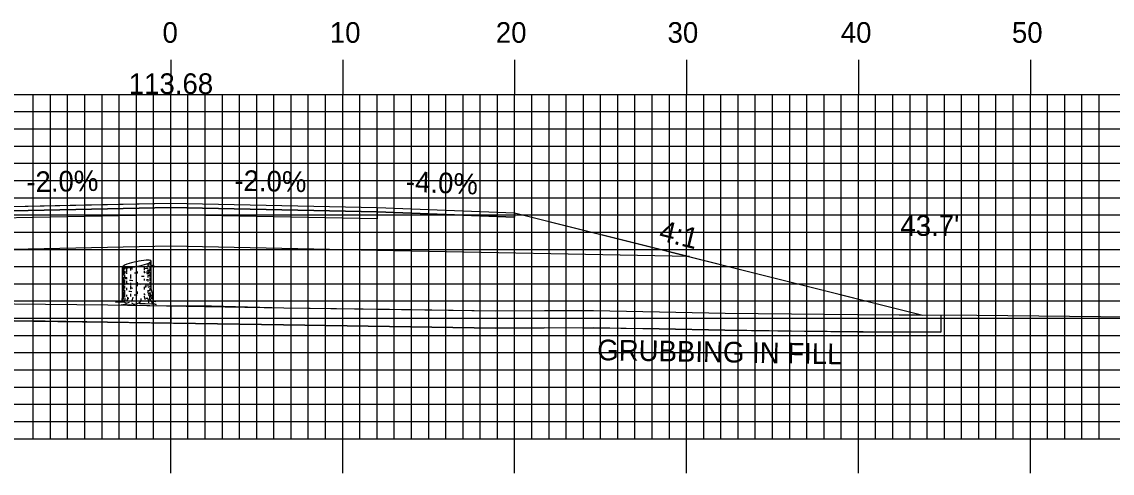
# Model space of a CAD drawing. Extents: x 1773203 to 1773546, y 442591 to 442811.
# Drawn here: x 1773360 to 1773423.4, y 442646.7 to 442672.9 of the extents above; entities that cross this region are included whole.
import ezdxf

# ---------------------------------------------------------------- set-up
doc = ezdxf.new("R2010")
doc.units = 0
for name, color, linetype in [('ANNOTATION', 7, 'Continuous'), ('D_Drainage_Culvert', 7, 'Continuous'), ('D_Roadway_Centerline', 7, 'Continuous'), ('D_Roadway_Centerline_Text', 7, 'Continuous'), ('D_Roadway_Edge_Shoulder', 7, 'Continuous'), ('D_Roadway_Edge_TW', 7, 'Continuous'), ('D_Roadway_Pavement', 7, 'Continuous'), ('D_Roadway_SubGrade', 7, 'Continuous'), ('D_Text_Standard', 7, 'Continuous'), ('GRUBBING IN FILL', 7, 'Continuous'), ('H_V ANNOTATION', 7, 'Continuous'), ('M_Trees_Conifer_Pay', 7, 'Continuous'), ('MAJOR', 7, 'Continuous'), ('MINOR', 7, 'Continuous'), ('S_Roadway_Centerline', 7, 'Continuous')]:
    doc.layers.add(name, color=color, linetype=linetype)

msp = doc.modelspace()

# ---------------------------------------------------------------- linework, layer by layer
at = {"layer": 'D_Drainage_Culvert'}
msp.add_line((1773380.633, 442662.104), (1773388.632, 442661.784), dxfattribs=at)
msp.add_lwpolyline([(1773388.632, 442661.784), (1773392.632, 442660.784), (1773412.369, 442655.85)], dxfattribs=at)
at = {"layer": 'D_Roadway_Centerline'}
msp.add_lwpolyline([(1773330.914, 442657.355), (1773338.457, 442659.24), (1773348.633, 442661.784), (1773348.633, 442661.784), (1773348.633, 442661.784), (1773352.008, 442661.919), (1773356.633, 442662.104), (1773363.648, 442662.245), (1773368.633, 442662.344), (1773380.633, 442662.104), (1773388.632, 442661.784), (1773388.632, 442661.784), (1773412.369, 442655.85)], dxfattribs=at)
at = {"layer": 'D_Roadway_Edge_Shoulder'}
msp.add_lwpolyline([(1773380.633, 442662.104), (1773388.632, 442661.784), (1773388.633, 442661.534), (1773380.633, 442661.854)], close=True, dxfattribs=at)
at = {"layer": 'D_Roadway_Edge_TW'}
msp.add_lwpolyline([(1773356.633, 442661.854), (1773356.633, 442662.104), (1773368.633, 442662.344), (1773380.633, 442662.104), (1773380.633, 442661.854), (1773368.633, 442662.094)], close=True, dxfattribs=at)
at = {"layer": 'D_Roadway_Pavement'}
msp.add_lwpolyline([(1773356.633, 442661.437), (1773356.633, 442661.854), (1773368.633, 442662.094), (1773380.633, 442661.854), (1773380.633, 442661.437), (1773368.633, 442661.677)], close=True, dxfattribs=at)
at = {"layer": 'D_Roadway_SubGrade'}
msp.add_lwpolyline([(1773356.633, 442659.604), (1773338.457, 442659.24), (1773348.633, 442661.784), (1773348.633, 442661.534), (1773356.633, 442661.854), (1773368.633, 442662.094), (1773380.633, 442661.854), (1773388.633, 442661.534), (1773388.632, 442661.784), (1773398.809, 442659.24), (1773380.633, 442659.604), (1773368.633, 442659.844)], close=True, dxfattribs=at)
at = {"layer": 'GRUBBING IN FILL'}
msp.add_line((1773413.42, 442655.845), (1773413.42, 442654.845), dxfattribs=at)
msp.add_line((1773413.42, 442655.845), (1773413.42, 442654.845), dxfattribs=at)
for points in [[(1773338.457, 442657.187), (1773343.237, 442657.056), (1773348.011, 442656.876), (1773352.869, 442656.7), (1773357.726, 442656.524), (1773361.346, 442656.483), (1773364.965, 442656.443), (1773368.633, 442656.382), (1773368.633, 442655.382), (1773364.952, 442655.443), (1773361.327, 442655.483), (1773357.703, 442655.524), (1773352.84, 442655.7), (1773347.977, 442655.877), (1773346.684, 442655.918), (1773340.829, 442656.122), (1773338.457, 442656.187)], [(1773338.457, 442657.187), (1773343.237, 442657.056), (1773348.011, 442656.876), (1773352.869, 442656.7), (1773357.726, 442656.524), (1773361.346, 442656.483), (1773364.965, 442656.443), (1773368.633, 442656.382), (1773368.633, 442655.382), (1773364.952, 442655.443), (1773361.327, 442655.483), (1773357.703, 442655.524), (1773352.84, 442655.7), (1773347.977, 442655.877), (1773346.684, 442655.918), (1773340.829, 442656.122), (1773338.457, 442656.187)], [(1773368.633, 442656.382), (1773371.006, 442656.382), (1773375.201, 442656.273), (1773381.356, 442656.18), (1773387.511, 442656.088), (1773390.365, 442656.103), (1773393.22, 442656.117), (1773397.053, 442656.041), (1773400.886, 442655.965), (1773404.733, 442655.917), (1773408.579, 442655.87), (1773413.42, 442655.845), (1773413.42, 442654.845), (1773410.995, 442654.857), (1773404.72, 442654.917), (1773400.869, 442654.965), (1773397.041, 442655.041), (1773390.359, 442655.103), (1773387.506, 442655.088), (1773381.345, 442655.18), (1773375.185, 442655.273), (1773370.068, 442655.358), (1773368.633, 442655.382)], [(1773368.633, 442656.382), (1773371.006, 442656.382), (1773375.201, 442656.273), (1773381.356, 442656.18), (1773387.511, 442656.088), (1773390.365, 442656.103), (1773393.22, 442656.117), (1773397.053, 442656.041), (1773400.886, 442655.965), (1773404.733, 442655.917), (1773408.579, 442655.87), (1773413.42, 442655.845), (1773413.42, 442654.845), (1773410.995, 442654.857), (1773404.72, 442654.917), (1773400.869, 442654.965), (1773397.041, 442655.041), (1773390.359, 442655.103), (1773387.506, 442655.088), (1773381.345, 442655.18), (1773375.185, 442655.273), (1773370.068, 442655.358), (1773368.633, 442655.382)]]:
    msp.add_lwpolyline(points, close=True, dxfattribs=at)
msp.add_lwpolyline([(1773338.457, 442656.187), (1773343.201, 442656.057), (1773345.391, 442655.959), (1773347.977, 442655.877), (1773357.703, 442655.524), (1773364.952, 442655.443), (1773375.185, 442655.273), (1773387.506, 442655.088), (1773393.213, 442655.117), (1773400.869, 442654.965), (1773408.571, 442654.87), (1773413.42, 442654.845)], dxfattribs=at)
msp.add_lwpolyline([(1773338.457, 442656.187), (1773343.201, 442656.057), (1773345.391, 442655.959), (1773347.977, 442655.877), (1773357.703, 442655.524), (1773364.952, 442655.443), (1773375.185, 442655.273), (1773387.506, 442655.088), (1773393.213, 442655.117), (1773400.869, 442654.965), (1773408.571, 442654.87), (1773413.42, 442654.845)], dxfattribs=at)
at = {"layer": 'M_Trees_Conifer_Pay'}
for p, q in [((1773365.83, 442656.924), (1773365.83, 442658.646)), ((1773367.077, 442658.652), (1773367.077, 442658.452)), ((1773367.305, 442658.848), (1773367.305, 442658.625)), ((1773367.423, 442658.909), (1773367.423, 442658.746)), ((1773367.423, 442658.679), (1773367.423, 442658.551)), ((1773367.494, 442657.334), (1773367.494, 442658.981)), ((1773365.877, 442658.608), (1773365.877, 442658.137)), ((1773365.877, 442658.073), (1773365.877, 442657.765)), ((1773365.936, 442658.597), (1773365.936, 442658.499)), ((1773365.936, 442658.425), (1773365.936, 442658.221)), ((1773365.936, 442658.163), (1773365.936, 442657.964)), ((1773366.061, 442658.589), (1773366.061, 442658.357)), ((1773366.061, 442658.316), (1773366.061, 442658.242)), ((1773366.281, 442658.61), (1773366.281, 442658.442)), ((1773366.281, 442658.205), (1773366.281, 442657.968)), ((1773366.686, 442658.378), (1773366.686, 442658.283)), ((1773367.077, 442658.394), (1773367.077, 442658.306)), ((1773367.305, 442658.536), (1773367.305, 442658.489)), ((1773367.305, 442658.154), (1773367.305, 442658.022)), ((1773367.362, 442658.353), (1773367.311, 442658.293)), ((1773367.423, 442658.364), (1773367.423, 442658.028)), ((1773365.877, 442657.717), (1773365.877, 442657.225)), ((1773365.936, 442657.917), (1773365.936, 442657.581)), ((1773365.936, 442657.528), (1773365.936, 442657.392)), ((1773366.061, 442657.839), (1773366.061, 442657.7)), ((1773366.061, 442657.429), (1773366.061, 442657.287)), ((1773366.281, 442657.723), (1773366.281, 442657.571)), ((1773366.281, 442657.528), (1773366.281, 442657.354)), ((1773366.686, 442657.765), (1773366.686, 442657.69)), ((1773366.686, 442657.665), (1773366.686, 442657.517)), ((1773367.077, 442657.958), (1773367.077, 442657.853)), ((1773367.077, 442657.486), (1773367.077, 442657.34)), ((1773367.305, 442657.911), (1773367.305, 442657.801)), ((1773367.305, 442657.665), (1773367.305, 442657.524)), ((1773367.423, 442657.991), (1773367.423, 442657.828)), ((1773367.423, 442657.781), (1773367.423, 442657.564)), ((1773367.423, 442657.534), (1773367.423, 442657.459)), ((1773367.423, 442657.419), (1773367.423, 442657.246)), ((1773365.877, 442657.171), (1773365.877, 442656.924)), ((1773365.936, 442657.293), (1773365.936, 442656.914)), ((1773366.061, 442657.025), (1773366.061, 442656.931)), ((1773366.281, 442657.077), (1773366.281, 442656.924)), ((1773366.686, 442657.225), (1773366.686, 442657.072)), ((1773367.077, 442657.108), (1773367.077, 442657.019)), ((1773367.305, 442657.297), (1773367.305, 442657.124)), ((1773366.061, 442656.531), (1773366.224, 442656.595)), ((1773366.498, 442656.467), (1773366.372, 442656.531))]:
    msp.add_line(p, q, dxfattribs=at)
for points in [[(1773367.311, 442658.479), (1773367.348, 442658.405), (1773367.395, 442658.462), (1773367.453, 442658.53), (1773367.545, 442658.724), (1773367.61, 442658.771), (1773367.64, 442658.778)], [(1773367.326, 442658.226), (1773367.362, 442658.353), (1773367.426, 442658.469), (1773367.457, 442658.536), (1773367.526, 442658.683)], [(1773367.54, 442658.712), (1773367.616, 442658.72), (1773367.688, 442658.621)], [(1773366.009, 442657.952), (1773366.003, 442658.047), (1773366.047, 442658.024), (1773366.047, 442657.929)], [(1773367.278, 442658.442), (1773367.247, 442658.357), (1773367.243, 442658.289), (1773367.274, 442658.226)], [(1773367.148, 442657.553), (1773367.161, 442657.476), (1773367.208, 442657.486), (1773367.196, 442657.653)], [(1773367.494, 442657.334), (1773367.545, 442657.072), (1773367.562, 442656.799), (1773367.619, 442656.673), (1773367.755, 442656.643), (1773367.525, 442656.605), (1773367.525, 442656.605), (1773367.531, 442656.558), (1773367.778, 442656.463), (1773367.504, 442656.48), (1773367.148, 442656.5), (1773366.827, 442656.49), (1773366.833, 442656.572), (1773366.685, 442656.49), (1773366.498, 442656.467), (1773366.522, 442656.399), (1773366.255, 442656.442), (1773366.034, 442656.415), (1773365.742, 442656.433), (1773366.03, 442656.49), (1773366.061, 442656.531), (1773365.898, 442656.589), (1773365.661, 442656.599), (1773365.421, 442656.599), (1773365.763, 442656.657), (1773365.804, 442656.737), (1773365.83, 442656.924)], [(1773365.878, 442656.877), (1773365.857, 442656.799), (1773365.837, 442656.704)], [(1773365.956, 442656.856), (1773365.962, 442656.741), (1773365.909, 442656.652), (1773365.898, 442656.589)], [(1773366.119, 442656.883), (1773366.119, 442656.751), (1773366.03, 442656.652)], [(1773366.345, 442656.643), (1773366.413, 442656.737), (1773366.44, 442656.877)], [(1773366.833, 442656.572), (1773366.908, 442656.714), (1773366.917, 442656.815)], [(1773367.084, 442656.941), (1773367.095, 442656.815), (1773367.169, 442656.772)], [(1773367.362, 442656.552), (1773367.348, 442656.69), (1773367.274, 442656.819)], [(1773367.321, 442657.046), (1773367.395, 442656.941), (1773367.4, 442656.768), (1773367.525, 442656.605)], [(1773367.42, 442657.192), (1773367.426, 442657.046), (1773367.473, 442656.978), (1773367.484, 442656.778)]]:
    msp.add_lwpolyline(points, dxfattribs=at)
for centre, radius, start, end in [((1773365.857, 442658.645), 0.0264, 169.2194, 180.03145), ((1773365.853, 442658.645), 0.0226, 180.03145, 191.7194), ((1773365.862, 442658.645), 0.0314, 156.51582, 169.2194), ((1773365.853, 442658.645), 0.0226, 191.7194, 203.40735), ((1773365.881, 442658.636), 0.0527, 146.7194, 156.51582), ((1773365.905, 442658.62), 0.0817, 132.38868, 146.7194), ((1773366.019, 442658.495), 0.251, 124.2194, 132.38868), ((1773366.329, 442658.04), 0.802, 108.05939, 124.2194), ((1773367.686, 442653.878), 5.179, 101.7194, 108.05939), ((1773365.638, 442663.749), 5.179, 275.37941, 281.7194), ((1773367.686, 442653.878), 5.179, 95.37941, 101.7194), ((1773365.638, 442663.749), 5.179, 281.7194, 288.05939), ((1773367.276, 442658.236), 0.802, 79.2194, 95.37941), ((1773366.995, 442659.587), 0.802, 288.05939, 304.2194), ((1773367.163, 442659.295), 0.571, 284.43166, 292.41325), ((1773367.163, 442659.14), 0.571, 297.0237, 300), ((1773367.379, 442658.777), 0.251, 71.05013, 79.2194), ((1773367.305, 442659.131), 0.251, 304.2194, 312.38868), ((1773367.362, 442658.95), 0.172, 300, 311.25059), ((1773367.362, 442658.795), 0.172, 300, 311.25059), ((1773367.434, 442658.937), 0.0817, 56.7194, 71.05013), ((1773367.419, 442659.007), 0.0817, 312.38868, 326.7194), ((1773367.435, 442658.867), 0.0624, 311.25059, 330), ((1773367.435, 442658.713), 0.0624, 311.25059, 330), ((1773367.449, 442658.961), 0.0527, 46.92298, 56.7194), ((1773367.464, 442658.977), 0.0314, 34.2194, 46.92298), ((1773367.443, 442658.991), 0.0527, 326.7194, 336.51582), ((1773367.451, 442658.858), 0.0441, 330, 343.94846), ((1773367.451, 442658.703), 0.0441, 330, 343.94846), ((1773367.468, 442658.98), 0.0264, 23.40735, 34.2194), ((1773367.472, 442658.981), 0.0226, 11.7194, 23.40735), ((1773367.463, 442658.982), 0.0314, 336.51582, 349.2194), ((1773367.461, 442658.855), 0.0334, 343.94846, 354.21506), ((1773367.461, 442658.7), 0.0334, 343.94846, 354.21506), ((1773367.472, 442658.981), 0.0226, 0.03145, 11.7194), ((1773367.468, 442658.981), 0.0264, 349.2194, 0.03145), ((1773365.862, 442658.468), 0.0334, 163.94846, 180), ((1773365.862, 442658.468), 0.0334, 180, 196.05154), ((1773365.862, 442658.021), 0.0334, 163.94846, 180), ((1773365.862, 442658.021), 0.0334, 180, 196.05154), ((1773365.873, 442658.47), 0.0441, 196.05154, 210), ((1773365.873, 442658.024), 0.0441, 196.05154, 210), ((1773365.856, 442658.647), 0.0264, 203.40735, 214.2194), ((1773365.86, 442658.65), 0.0314, 214.2194, 226.92298), ((1773365.888, 442658.48), 0.0624, 210, 228.74941), ((1773365.875, 442658.665), 0.0527, 226.92298, 236.7194), ((1773365.891, 442658.69), 0.0817, 236.7194, 251.05013), ((1773365.961, 442658.562), 0.172, 228.74941, 240), ((1773365.946, 442658.849), 0.251, 251.05013, 259.2194), ((1773366.16, 442658.907), 0.571, 240, 240.33672), ((1773366.161, 442658.696), 0.571, 240, 247.05866), ((1773366.049, 442659.391), 0.802, 259.2194, 275.37941), ((1773366.16, 442658.907), 0.571, 246.85973, 257.98457), ((1773366.662, 442662.658), 4.124, 264.6955, 266.73309), ((1773366.661, 442662.425), 4.124, 268.07512, 270), ((1773366.661, 442662.425), 4.124, 270, 270.35814), ((1773366.662, 442662.214), 4.124, 273.70524, 275.95043), ((1773366.661, 442662.425), 4.124, 275.78493, 277.05584), ((1773366.662, 442662.658), 4.124, 276.23804, 278.1032), ((1773367.163, 442659.14), 0.571, 278.1032, 284.36665), ((1773367.163, 442658.696), 0.571, 284.44928, 297.04285), ((1773367.449, 442658.024), 0.0441, 330, 343.94846), ((1773367.46, 442658.021), 0.0334, 343.94846, 354.21506), ((1773367.461, 442658.256), 0.0334, 343.94846, 354.21506), ((1773365.862, 442657.811), 0.0334, 163.94846, 180), ((1773365.862, 442657.811), 0.0334, 180, 196.05154), ((1773365.862, 442657.574), 0.0334, 163.94846, 180), ((1773365.862, 442657.574), 0.0334, 180, 196.05154), ((1773365.862, 442657.376), 0.0334, 163.94846, 180), ((1773365.873, 442657.814), 0.0441, 196.05154, 210), ((1773365.873, 442657.577), 0.0441, 196.05154, 210), ((1773365.888, 442658.033), 0.0624, 210, 228.74941), ((1773365.888, 442657.823), 0.0624, 210, 228.74941), ((1773365.888, 442657.586), 0.0624, 210, 228.74941), ((1773365.961, 442658.115), 0.172, 228.74941, 240), ((1773365.961, 442657.905), 0.172, 228.74941, 240), ((1773365.961, 442657.669), 0.172, 228.74941, 240), ((1773366.16, 442658.461), 0.571, 240, 240.33672), ((1773366.16, 442658.25), 0.571, 240, 246.85973), ((1773366.16, 442658.014), 0.571, 240, 246.85973), ((1773366.16, 442658.25), 0.571, 259.27072, 261.8968), ((1773366.661, 442661.768), 4.124, 261.8968, 263.14738), ((1773366.661, 442661.978), 4.124, 264.08098, 266.66759), ((1773366.661, 442661.531), 4.124, 264.71603, 266.31934), ((1773366.661, 442661.768), 4.124, 270, 270.35814), ((1773366.661, 442661.768), 4.124, 273.14934, 275.45691), ((1773366.661, 442661.978), 4.124, 277.61247, 278.1032), ((1773367.162, 442658.461), 0.571, 278.1032, 286.92962), ((1773367.162, 442658.014), 0.571, 285.39827, 297.18959), ((1773367.162, 442658.461), 0.571, 297.18959, 300), ((1773367.162, 442658.25), 0.571, 297.18959, 300), ((1773367.361, 442658.115), 0.172, 300, 311.25059), ((1773367.361, 442657.905), 0.172, 300, 311.25059), ((1773367.433, 442658.033), 0.0624, 311.25059, 330), ((1773367.433, 442657.823), 0.0624, 311.25059, 330), ((1773367.449, 442657.814), 0.0441, 330, 343.94846), ((1773367.46, 442657.811), 0.0334, 343.94846, 354.21506), ((1773367.46, 442657.376), 0.0334, 343.94846, 354.21506), ((1773365.862, 442657.181), 0.0334, 163.94846, 180), ((1773365.862, 442657.181), 0.0334, 180, 196.05154), ((1773365.862, 442656.96), 0.0334, 163.94846, 180), ((1773365.862, 442656.96), 0.0334, 180, 196.05154), ((1773365.873, 442657.184), 0.0441, 196.05154, 210), ((1773365.873, 442656.963), 0.0441, 196.05154, 210), ((1773365.888, 442657.193), 0.0624, 210, 228.74941), ((1773365.888, 442656.972), 0.0624, 210, 228.74941), ((1773365.961, 442657.275), 0.172, 228.74941, 240), ((1773365.961, 442657.055), 0.172, 228.74941, 240), ((1773366.149, 442657.822), 0.571, 241.23686, 248.02677), ((1773366.16, 442657.62), 0.571, 240, 246.85973), ((1773366.16, 442657.4), 0.571, 240, 244.53138), ((1773366.661, 442660.918), 4.124, 262.44379, 263.51202), ((1773366.661, 442661.334), 4.124, 263.49906, 265.83975), ((1773366.661, 442661.138), 4.124, 267.81166, 270), ((1773366.661, 442661.138), 4.124, 270, 270.13279), ((1773366.661, 442661.138), 4.124, 275.78493, 276.78961), ((1773366.661, 442660.918), 4.124, 277.36842, 278.1032), ((1773367.162, 442657.4), 0.571, 278.1032, 281.63703), ((1773367.162, 442657.62), 0.571, 288.50673, 297.27208), ((1773367.162, 442657.816), 0.571, 289.29072, 300), ((1773367.361, 442657.471), 0.172, 300, 311.25059), ((1773367.361, 442657.055), 0.172, 300, 311.25059), ((1773367.433, 442657.388), 0.0624, 311.25059, 330), ((1773367.433, 442656.972), 0.0624, 311.25059, 330), ((1773367.449, 442657.379), 0.0441, 330, 343.94846), ((1773367.449, 442656.963), 0.0441, 330, 343.94846), ((1773367.46, 442656.96), 0.0334, 343.94846, 354.21506)]:
    msp.add_arc(centre, radius, start, end, dxfattribs=at)
at = {"layer": 'MAJOR'}
for p, q in [((1773368.633, 442670.669), (1773368.633, 442668.665)), ((1773378.633, 442670.669), (1773378.633, 442668.665)), ((1773388.633, 442670.669), (1773388.633, 442668.665)), ((1773398.633, 442670.669), (1773398.633, 442668.665)), ((1773408.633, 442670.669), (1773408.633, 442668.665)), ((1773418.633, 442670.669), (1773418.633, 442668.665)), ((1773228.633, 442668.665), (1773508.633, 442668.665)), ((1773228.633, 442668.665), (1773508.633, 442668.665)), ((1773368.633, 442648.665), (1773368.633, 442668.665)), ((1773378.633, 442648.665), (1773378.633, 442668.665)), ((1773388.633, 442648.665), (1773388.633, 442668.665)), ((1773398.633, 442648.665), (1773398.633, 442668.665)), ((1773408.633, 442648.665), (1773408.633, 442668.665)), ((1773418.633, 442648.665), (1773418.633, 442668.665)), ((1773228.633, 442663.665), (1773508.633, 442663.665)), ((1773228.633, 442658.665), (1773508.633, 442658.665)), ((1773228.633, 442653.665), (1773508.633, 442653.665)), ((1773228.633, 442648.665), (1773508.633, 442648.665)), ((1773228.633, 442648.665), (1773508.633, 442648.665)), ((1773368.633, 442646.661), (1773368.633, 442648.665)), ((1773378.633, 442646.661), (1773378.633, 442648.665)), ((1773388.633, 442646.661), (1773388.633, 442648.665)), ((1773398.633, 442646.661), (1773398.633, 442648.665)), ((1773408.633, 442646.661), (1773408.633, 442648.665)), ((1773418.633, 442646.661), (1773418.633, 442648.665))]:
    msp.add_line(p, q, dxfattribs=at)
at = {"layer": 'MINOR'}
for p, q in [((1773360.633, 442648.665), (1773360.633, 442668.665)), ((1773361.633, 442648.665), (1773361.633, 442668.665)), ((1773362.633, 442648.665), (1773362.633, 442668.665)), ((1773363.633, 442648.665), (1773363.633, 442668.665)), ((1773364.633, 442648.665), (1773364.633, 442668.665)), ((1773365.633, 442648.665), (1773365.633, 442668.665)), ((1773366.633, 442648.665), (1773366.633, 442668.665)), ((1773367.633, 442648.665), (1773367.633, 442668.665)), ((1773369.633, 442648.665), (1773369.633, 442668.665)), ((1773370.633, 442648.665), (1773370.633, 442668.665)), ((1773371.633, 442648.665), (1773371.633, 442668.665)), ((1773372.633, 442648.665), (1773372.633, 442668.665)), ((1773373.633, 442648.665), (1773373.633, 442668.665)), ((1773374.633, 442648.665), (1773374.633, 442668.665)), ((1773375.633, 442648.665), (1773375.633, 442668.665)), ((1773376.633, 442648.665), (1773376.633, 442668.665)), ((1773377.633, 442648.665), (1773377.633, 442668.665)), ((1773379.633, 442648.665), (1773379.633, 442668.665)), ((1773380.633, 442648.665), (1773380.633, 442668.665)), ((1773381.633, 442648.665), (1773381.633, 442668.665)), ((1773382.633, 442648.665), (1773382.633, 442668.665)), ((1773383.633, 442648.665), (1773383.633, 442668.665)), ((1773384.633, 442648.665), (1773384.633, 442668.665)), ((1773385.633, 442648.665), (1773385.633, 442668.665)), ((1773386.633, 442648.665), (1773386.633, 442668.665)), ((1773387.633, 442648.665), (1773387.633, 442668.665)), ((1773389.633, 442648.665), (1773389.633, 442668.665)), ((1773390.633, 442648.665), (1773390.633, 442668.665)), ((1773391.633, 442648.665), (1773391.633, 442668.665)), ((1773392.633, 442648.665), (1773392.633, 442668.665)), ((1773393.633, 442648.665), (1773393.633, 442668.665)), ((1773394.633, 442648.665), (1773394.633, 442668.665)), ((1773395.633, 442648.665), (1773395.633, 442668.665)), ((1773396.633, 442648.665), (1773396.633, 442668.665)), ((1773397.633, 442648.665), (1773397.633, 442668.665)), ((1773399.633, 442648.665), (1773399.633, 442668.665)), ((1773400.633, 442648.665), (1773400.633, 442668.665)), ((1773401.633, 442648.665), (1773401.633, 442668.665)), ((1773402.633, 442648.665), (1773402.633, 442668.665)), ((1773403.633, 442648.665), (1773403.633, 442668.665)), ((1773404.633, 442648.665), (1773404.633, 442668.665)), ((1773405.633, 442648.665), (1773405.633, 442668.665)), ((1773406.633, 442648.665), (1773406.633, 442668.665)), ((1773407.633, 442648.665), (1773407.633, 442668.665)), ((1773409.633, 442648.665), (1773409.633, 442668.665)), ((1773410.633, 442648.665), (1773410.633, 442668.665)), ((1773411.633, 442648.665), (1773411.633, 442668.665)), ((1773412.633, 442648.665), (1773412.633, 442668.665)), ((1773413.633, 442648.665), (1773413.633, 442668.665)), ((1773414.633, 442648.665), (1773414.633, 442668.665)), ((1773415.633, 442648.665), (1773415.633, 442668.665)), ((1773416.633, 442648.665), (1773416.633, 442668.665)), ((1773417.633, 442648.665), (1773417.633, 442668.665)), ((1773419.633, 442648.665), (1773419.633, 442668.665)), ((1773420.633, 442648.665), (1773420.633, 442668.665)), ((1773421.633, 442648.665), (1773421.633, 442668.665)), ((1773422.633, 442648.665), (1773422.633, 442668.665)), ((1773228.633, 442667.665), (1773508.633, 442667.665)), ((1773228.633, 442666.665), (1773508.633, 442666.665)), ((1773228.633, 442665.665), (1773508.633, 442665.665)), ((1773228.633, 442664.665), (1773508.633, 442664.665)), ((1773228.633, 442662.665), (1773508.633, 442662.665)), ((1773228.633, 442661.665), (1773508.633, 442661.665)), ((1773228.633, 442660.665), (1773508.633, 442660.665)), ((1773228.633, 442659.665), (1773508.633, 442659.665)), ((1773228.633, 442657.665), (1773508.633, 442657.665)), ((1773228.633, 442656.665), (1773508.633, 442656.665)), ((1773228.633, 442655.665), (1773508.633, 442655.665)), ((1773228.633, 442654.665), (1773508.633, 442654.665)), ((1773228.633, 442652.665), (1773508.633, 442652.665)), ((1773228.633, 442651.665), (1773508.633, 442651.665)), ((1773228.633, 442650.665), (1773508.633, 442650.665)), ((1773228.633, 442649.665), (1773508.633, 442649.665))]:
    msp.add_line(p, q, dxfattribs=at)
at = {"layer": 'S_Roadway_Centerline'}
msp.add_lwpolyline([(1773308.945, 442657.68), (1773313.177, 442657.559), (1773326.715, 442657.389), (1773332.969, 442657.338), (1773343.237, 442657.056), (1773345.429, 442656.958), (1773348.011, 442656.876), (1773357.726, 442656.524), (1773364.965, 442656.443), (1773375.201, 442656.273), (1773387.511, 442656.088), (1773393.22, 442656.117), (1773400.886, 442655.965), (1773408.579, 442655.87), (1773415.52, 442655.834), (1773424.52, 442655.74)], dxfattribs=at)

# ---------------------------------------------------------------- texts
at = {"layer": 'ANNOTATION'}
for s, rotation, p in [('-2.0%', 1.14579, (1773360.239, 442662.977)), ('-2.0%', 358.85428, (1773372.319, 442663.071)), ('-4.0%', 357.70921, (1773382.288, 442663.015)), ('4:1', 345.96275, (1773396.969, 442660.209))]:
    msp.add_text(s, height=1.2, rotation=rotation, dxfattribs=at).set_placement(p)
at = {"layer": 'D_Roadway_Centerline'}
for s, p in [('C', (1773368.627, 442662.344)), ('L', (1773368.633, 442662.337))]:
    msp.add_text(s, height=0.0146, dxfattribs=at).set_placement(p)
at = {"layer": 'D_Roadway_Centerline_Text'}
msp.add_text('113.68', height=1.2, dxfattribs=at).set_placement((1773366.188, 442668.691))
at = {"layer": 'D_Text_Standard'}
msp.add_text("43.7'", height=1.2, dxfattribs=at).set_placement((1773411.074, 442660.448))
at = {"layer": 'GRUBBING IN FILL'}
msp.add_text('GRUBBING IN FILL', height=1.2, rotation=359.01917, dxfattribs=at).set_placement((1773393.431, 442653.227))
at = {"layer": 'H_V ANNOTATION'}
for s, p in [('0', (1773368.151, 442671.665)), ('10', (1773377.884, 442671.665)), ('20', (1773387.541, 442671.665)), ('30', (1773397.53, 442671.665)), ('40', (1773407.605, 442671.665)), ('50', (1773417.562, 442671.665))]:
    msp.add_text(s, height=1.2, dxfattribs=at).set_placement(p)

doc.saveas('drawing.dxf')
